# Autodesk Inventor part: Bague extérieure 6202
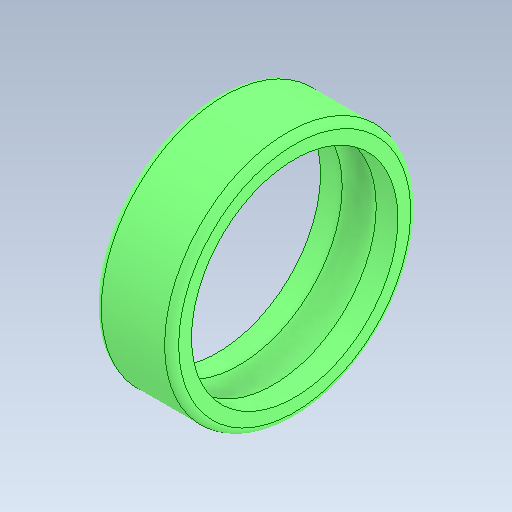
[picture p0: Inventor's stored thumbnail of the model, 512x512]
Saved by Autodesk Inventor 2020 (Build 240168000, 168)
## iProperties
Created: 2003-06
Part Number: Bague extérieure 6202
Material: Générique
Document SubType Name: Modeling
Designer: Bruno
Density: 1 g/cm^3
Appearance: Par défaut
Author: Bruno
Sending System: SolidWorks 2011
Last Author: Professeur
Last Saved: 2014-11-10
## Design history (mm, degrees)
feature "Base-Révolution"
node "Solide1"
